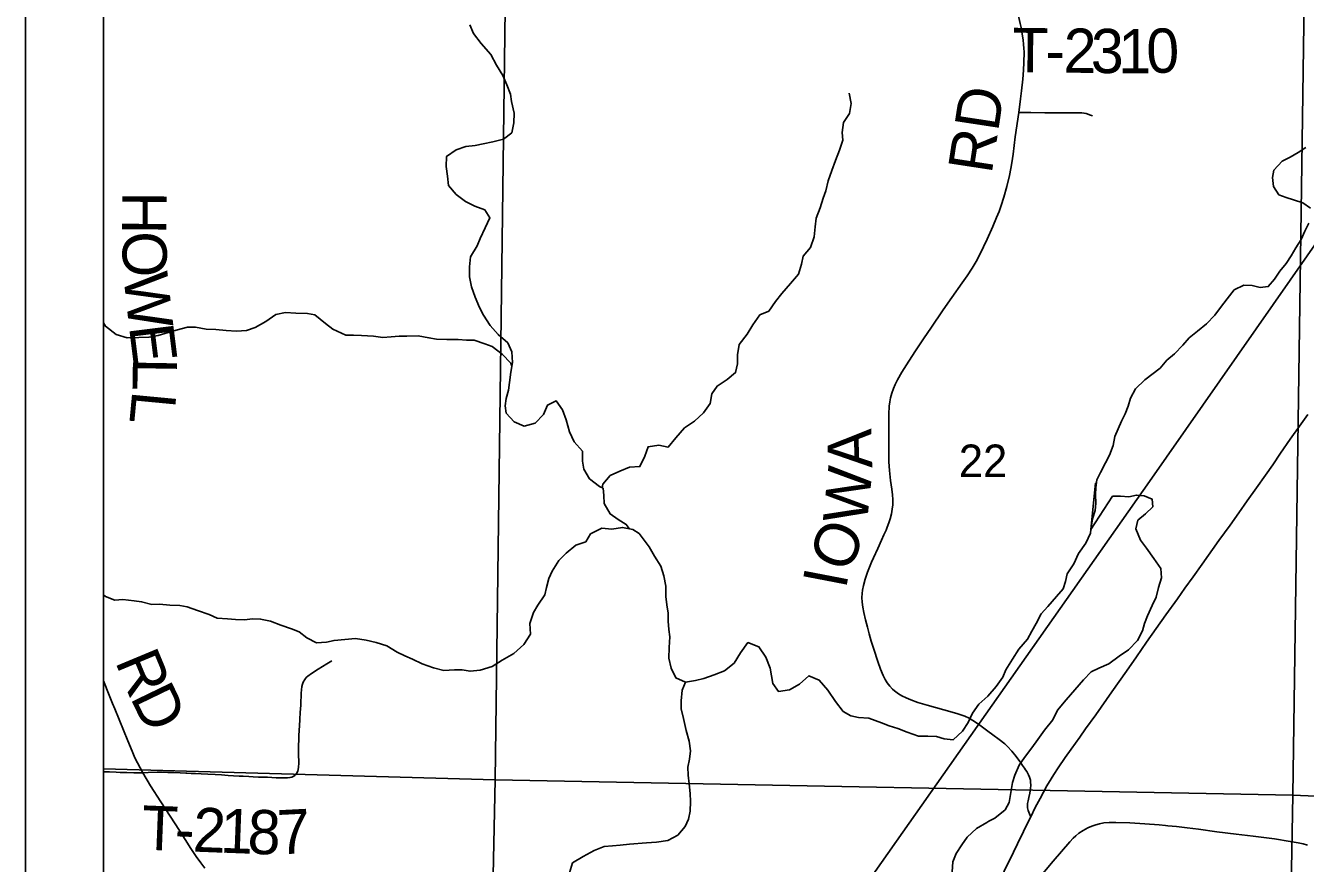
# Model space of a CAD drawing. Extents: x 0 to 34, y 0 to 22.
# Drawn here: x 23.417 to 25.06, y 16.636 to 17.712 of the extents above; entities that cross this region are included whole.
import ezdxf

# ---------------------------------------------------------------- set-up
doc = ezdxf.new("R2010")
doc.units = 0
for name, color, linetype in [('GM_X_Corporation', 7, 'Continuous'), ('GM_X_County_Road', 7, 'Continuous'), ('GM_X_County_Road_Text', 7, 'Continuous'), ('GM_X_Minor_River', 7, 'Continuous'), ('GM_X_Rail_Line', 7, 'Continuous'), ('GM_X_Section_Text', 7, 'Continuous'), ('GM_X_State_Route', 7, 'Continuous'), ('GM_X_Township_Road', 7, 'Continuous'), ('GM_X_Township_Road_Text', 7, 'Continuous'), ('SH_Data', 7, 'Continuous')]:
    doc.layers.add(name, color=color, linetype=linetype)

msp = doc.modelspace()

# ---------------------------------------------------------------- linework, layer by layer
at = {"layer": 'GM_X_Corporation'}
for points in [[(30.3167, 20.9), (23.5167, 20.9), (23.5167, 14.7114), (24.6586, 14.6808), (24.6805, 14.6799), (26.0522, 14.6391), (26.4447, 14.6283), (26.4468, 14.6272), (26.4498, 14.6263), (26.4544, 14.6257), (26.5226, 14.6248), (26.5325, 14.6248), (26.5616, 14.6241), (26.5684, 14.624), (26.5727, 14.624), (26.5813, 14.6239), (26.5991, 14.6234), (26.6128, 14.6229), (26.6208, 14.6225), (26.6337, 14.622), (26.643, 14.6216), (26.6535, 14.621), (27.01, 14.6164)], [(23.5167, 20.7862), (23.5167, 14.7114), (24.6586, 14.6808), (24.6805, 14.6799), (26.0522, 14.6391), (26.4447, 14.6283), (26.4468, 14.6272), (26.4498, 14.6263), (26.4544, 14.6257), (26.5226, 14.6248), (26.5325, 14.6248), (26.5616, 14.6241), (26.5684, 14.624), (26.5727, 14.624), (26.5813, 14.6239), (26.5991, 14.6234), (26.6128, 14.6229), (26.6208, 14.6225), (26.6337, 14.622), (26.643, 14.6216), (26.6535, 14.621), (27.01, 14.6164)]]:
    msp.add_lwpolyline(points, dxfattribs=at)
for points in [[(23.5167, 17.7813), (23.5167, 16.7576), (24.0196, 16.7435), (24.0329, 17.7663)], [(24.0329, 17.7663), (25.0591, 17.7438), (25.0442, 16.7237), (24.0196, 16.7435)], [(26.075, 17.7146), (26.0652, 16.6798), (25.0442, 16.7237), (25.0591, 17.7438)], [(23.5167, 16.7576), (23.5167, 15.7361), (23.9985, 15.7225), (24.0196, 16.7435)], [(24.0196, 16.7435), (25.0442, 16.7237), (25.0261, 15.6992), (23.9985, 15.7225)], [(25.0442, 16.7237), (26.0652, 16.6798), (26.0458, 15.6621), (25.0261, 15.6992)]]:
    msp.add_lwpolyline(points, close=True, dxfattribs=at)
at = {"layer": 'GM_X_County_Road'}
for points in [[(23.5673, 16.7525), (23.5571, 16.772), (23.5534, 16.7805), (23.5479, 16.7937), (23.5312, 16.8346), (23.5284, 16.8415), (23.524, 16.8524), (23.5167, 16.8705)], [(23.6469, 16.6302), (23.6416, 16.637), (23.6358, 16.6451), (23.629, 16.6555), (23.6143, 16.6785), (23.5903, 16.7155), (23.5773, 16.7359), (23.5673, 16.7525)]]:
    msp.add_lwpolyline(points, dxfattribs=at)
at = {"layer": 'GM_X_Minor_River'}
for points in [[(24.1586, 17.1181), (24.1537, 17.1203), (24.1411, 17.1301), (24.1338, 17.1426), (24.1318, 17.1528), (24.1318, 17.1657), (24.1211, 17.1774), (24.1153, 17.1903), (24.111, 17.2058), (24.1064, 17.2187), (24.0983, 17.23), (24.087, 17.2246), (24.0818, 17.2128), (24.0712, 17.2017), (24.0572, 17.1978), (24.0443, 17.2031), (24.034, 17.2144), (24.0328, 17.2239), (24.0339, 17.2334), (24.0368, 17.244), (24.0383, 17.2539), (24.0401, 17.2668), (24.0419, 17.2793), (24.041, 17.293), (24.036, 17.3047), (24.0238, 17.3153), (24.0135, 17.327), (24.0047, 17.3402), (23.9997, 17.35), (23.9939, 17.3633), (23.9893, 17.3765), (23.9869, 17.3894), (23.9868, 17.4023), (23.9883, 17.4152), (23.9965, 17.429), (24.0006, 17.4385), (24.007, 17.4522), (24.013, 17.4651), (24.0064, 17.4753), (23.9935, 17.4802), (23.9817, 17.4862), (23.9695, 17.4952), (23.96, 17.5065), (23.9584, 17.5187), (23.9568, 17.5312), (23.9574, 17.5441), (23.9699, 17.5525), (23.982, 17.5568), (23.9941, 17.558), (24.0043, 17.56), (24.0168, 17.5627), (24.0305, 17.5662), (24.041, 17.5743), (24.0436, 17.5872), (24.0443, 17.5997), (24.0407, 17.6145), (24.0395, 17.624), (24.0349, 17.6361), (24.0295, 17.6478), (24.0215, 17.6611), (24.0142, 17.6747), (24.002, 17.689), (23.992, 17.7018), (23.9874, 17.7128)], [(24.1574, 17.1186), (24.1582, 17.1234), (24.1676, 17.1344), (24.1801, 17.1398), (24.1922, 17.1452), (24.2058, 17.1457), (24.2122, 17.159), (24.2163, 17.1712), (24.2299, 17.1732), (24.242, 17.1706), (24.2518, 17.1828), (24.2631, 17.1954), (24.2759, 17.2042), (24.2876, 17.2146), (24.2959, 17.2268), (24.2981, 17.2393), (24.3048, 17.2492), (24.3177, 17.2577), (24.3286, 17.2665), (24.3312, 17.2775), (24.3311, 17.2893), (24.3333, 17.3026), (24.3434, 17.3159), (24.3509, 17.3277), (24.3599, 17.3407), (24.3713, 17.3453), (24.3799, 17.3579), (24.3882, 17.3678), (24.3991, 17.3808), (24.4092, 17.3927), (24.4133, 17.4056), (24.4152, 17.4159), (24.4249, 17.4269), (24.4294, 17.4406), (24.4308, 17.4535), (24.4323, 17.4646), (24.4371, 17.4779), (24.4412, 17.4904), (24.4445, 17.4999), (24.4475, 17.5125), (24.4523, 17.5258), (24.4568, 17.5387), (24.462, 17.5521), (24.4665, 17.565), (24.4656, 17.5749), (24.4671, 17.5874), (24.4749, 17.5992), (24.4771, 17.6118), (24.4744, 17.6254)], [(25.067, 17.4774), (25.0571, 17.4845), (25.0454, 17.4882), (25.0359, 17.4911), (25.0264, 17.4948), (25.0195, 17.5053), (25.0183, 17.5171), (25.0201, 17.5265), (25.0306, 17.538), (25.0411, 17.5431), (25.0513, 17.5492), (25.0611, 17.5554)], [(24.7849, 17.0652), (24.787, 17.0789), (24.7903, 17.0892), (24.7914, 17.0987), (24.7909, 17.1093), (24.7912, 17.1188), (24.7926, 17.1286), (24.7971, 17.1381), (24.8038, 17.1507), (24.809, 17.1606), (24.8134, 17.1728), (24.8156, 17.1842), (24.82, 17.1941), (24.8241, 17.204), (24.8289, 17.2135), (24.833, 17.2234), (24.8359, 17.2337), (24.8422, 17.2455), (24.8542, 17.257), (24.8738, 17.2723), (24.8827, 17.2823), (24.8925, 17.2907), (24.903, 17.3018), (24.9112, 17.3113), (24.9221, 17.3198), (24.9334, 17.329), (24.9442, 17.3401), (24.9513, 17.35), (24.9599, 17.3611), (24.9689, 17.3726), (24.9813, 17.3788), (24.9919, 17.3781), (25.0025, 17.3756), (25.0127, 17.3768), (25.021, 17.3864), (25.0277, 17.3967), (25.0359, 17.4066), (25.0422, 17.4165), (25.0482, 17.4268), (25.0549, 17.4375), (25.0597, 17.4482), (25.0649, 17.4584)], [(24.0412, 17.2746), (24.04, 17.2786), (24.0289, 17.2903), (24.016, 17.3), (24.0065, 17.3034), (23.9928, 17.3079), (23.9829, 17.3082), (23.9723, 17.3089), (23.9579, 17.3091), (23.9443, 17.3094), (23.9348, 17.3113), (23.9207, 17.3138), (23.9063, 17.3133), (23.8965, 17.3133), (23.8862, 17.3125), (23.8756, 17.3116), (23.8635, 17.3131), (23.8483, 17.3141), (23.8377, 17.3144), (23.8278, 17.3147), (23.8115, 17.3222), (23.8019, 17.3297), (23.7882, 17.3406), (23.7787, 17.3425), (23.7639, 17.3427), (23.7507, 17.3434), (23.7382, 17.3411), (23.7254, 17.3319), (23.7114, 17.3242), (23.7004, 17.3203), (23.6875, 17.3195), (23.6742, 17.3205), (23.661, 17.3219), (23.6488, 17.3222), (23.6348, 17.3248), (23.6246, 17.3247), (23.6102, 17.3208), (23.6, 17.3181), (23.5871, 17.3142), (23.575, 17.3119), (23.5621, 17.3114), (23.5473, 17.3113), (23.5329, 17.3154), (23.5195, 17.3259), (23.5167, 17.3305)], [(24.1918, 17.0661), (24.1881, 17.0716), (24.1778, 17.0779), (24.1676, 17.0851), (24.1599, 17.0983), (24.1594, 17.1086), (24.1586, 17.1181)], [(24.8429, 17.0658), (24.8452, 17.0769), (24.855, 17.085), (24.8647, 17.0942), (24.8635, 17.104), (24.8533, 17.1084), (24.8434, 17.1091), (24.8336, 17.1071), (24.823, 17.1077), (24.8128, 17.1076), (24.7849, 17.0652), (24.7908, 17.1244), (24.7915, 17.1233)], [(24.2048, 17.0599), (24.1965, 17.0652), (24.1832, 17.0677), (24.1696, 17.0654), (24.1567, 17.0668), (24.1424, 17.0593)], [(24.6525, 16.8509), (24.6632, 16.8636), (24.6718, 16.8755), (24.6759, 16.885), (24.6842, 16.8983), (24.6924, 16.9113), (24.7037, 16.9243), (24.7089, 16.9346), (24.7145, 16.9445), (24.7213, 16.9567), (24.7295, 16.9662), (24.7408, 16.9788), (24.7495, 16.9888), (24.7524, 16.9983), (24.7546, 17.0082), (24.7629, 17.0208), (24.7692, 17.0341), (24.7786, 17.0475), (24.7846, 17.0604), (24.7849, 17.0652)], [(24.6537, 16.6906), (24.6617, 16.6944), (24.6749, 16.7051), (24.6802, 16.7146), (24.6827, 16.7298), (24.6842, 16.7401), (24.6871, 16.7496), (24.6927, 16.7622), (24.6998, 16.7721), (24.7092, 16.7847), (24.7167, 16.7954), (24.7254, 16.8072), (24.7359, 16.8206), (24.7419, 16.8331), (24.7531, 16.8465), (24.7644, 16.8591), (24.7753, 16.8721), (24.7855, 16.8821), (24.7953, 16.8871), (24.8078, 16.8925), (24.8214, 16.9025), (24.8331, 16.9105), (24.8447, 16.9224), (24.8511, 16.935), (24.8537, 16.9445), (24.8578, 16.954), (24.8637, 16.9673), (24.869, 16.978), (24.8719, 16.9905), (24.8756, 17.0031), (24.8748, 17.0148), (24.8656, 17.0277), (24.8564, 17.0409), (24.8487, 17.0514), (24.8429, 17.0658)], [(24.1424, 17.0593), (24.1361, 17.049), (24.1232, 17.0447), (24.1112, 17.0348), (24.1015, 17.0252), (24.0929, 17.0114), (24.0889, 17.0019), (24.0856, 16.9905), (24.0838, 16.981), (24.0748, 16.968), (24.0689, 16.9585), (24.0645, 16.9444), (24.065, 16.9308), (24.0568, 16.9174), (24.0437, 16.9056), (24.029, 16.8971), (24.0158, 16.8893), (24.0007, 16.8843), (23.9875, 16.883), (23.9773, 16.8848), (23.9674, 16.8847), (23.9538, 16.8841), (23.9405, 16.8874), (23.9261, 16.8926), (23.9136, 16.8985), (23.9037, 16.9026), (23.8938, 16.9074), (23.8808, 16.9156), (23.8668, 16.92), (23.8539, 16.9229), (23.8406, 16.925), (23.8266, 16.9237), (23.813, 16.9225), (23.8032, 16.9205), (23.7903, 16.9196), (23.7778, 16.9259), (23.7682, 16.9337), (23.7583, 16.9374), (23.7447, 16.9422), (23.7314, 16.9474), (23.7185, 16.9499), (23.7083, 16.9502), (23.6977, 16.9489), (23.6863, 16.9496), (23.6761, 16.9502), (23.6628, 16.9512), (23.6526, 16.956), (23.6374, 16.9612), (23.6241, 16.9656), (23.6146, 16.9674), (23.6021, 16.968), (23.5885, 16.969), (23.5786, 16.9689), (23.5657, 16.9722), (23.5562, 16.9732), (23.5415, 16.975), (23.5313, 16.9741), (23.5191, 16.9789), (23.5167, 16.9811)], [(24.6521, 16.8505), (24.6525, 16.8509), (24.6412, 16.8409), (24.633, 16.8291), (24.6275, 16.8173), (24.62, 16.8062), (24.608, 16.7951), (24.5966, 16.7961), (24.5868, 16.7994), (24.5754, 16.7997), (24.5637, 16.7996), (24.5489, 16.8047), (24.5371, 16.8095), (24.5257, 16.8128), (24.5162, 16.8169), (24.4999, 16.8228), (24.4866, 16.8238), (24.4767, 16.8256), (24.4668, 16.8315), (24.4569, 16.8443), (24.4469, 16.8586), (24.4361, 16.8714), (24.4228, 16.8773), (24.4105, 16.8662), (24.3977, 16.8592), (24.3837, 16.8572), (24.3764, 16.8673), (24.3732, 16.887), (24.3673, 16.901), (24.3585, 16.9145), (24.3444, 16.9197), (24.3347, 16.9067), (24.3269, 16.8934), (24.3145, 16.8837), (24.301, 16.8783), (24.2878, 16.8736), (24.2772, 16.8712), (24.2643, 16.8688), (24.2518, 16.8744), (24.246, 16.8868), (24.2428, 16.8997), (24.2431, 16.9137), (24.2441, 16.927), (24.2428, 16.9368), (24.242, 16.9474), (24.2422, 16.9577), (24.2402, 16.9683), (24.239, 16.9789), (24.2388, 16.9921), (24.2364, 17.0054), (24.2325, 17.0178), (24.2244, 17.0306), (24.2175, 17.0427), (24.2048, 17.0599)], [(24.2643, 16.8688), (24.2599, 16.8589), (24.2589, 16.8449), (24.2586, 16.8346), (24.2618, 16.8222), (24.265, 16.807), (24.2689, 16.7931), (24.2709, 16.7806), (24.2695, 16.7703), (24.2674, 16.7597), (24.2678, 16.7495), (24.2691, 16.7385), (24.2704, 16.726), (24.2708, 16.7157), (24.2702, 16.7032), (24.268, 16.693), (24.264, 16.6835), (24.2546, 16.6727), (24.2414, 16.6658), (24.2271, 16.6637), (24.2142, 16.6628), (24.1923, 16.6611), (24.1802, 16.6595), (24.1704, 16.659), (24.1598, 16.6581), (24.147, 16.653), (24.1327, 16.6453), (24.1191, 16.6368), (24.1151, 16.6243)], [(24.6537, 16.6906), (24.6515, 16.6887), (24.6379, 16.6813), (24.6259, 16.6698), (24.6192, 16.6603), (24.6118, 16.6488), (24.6077, 16.6382), (24.6067, 16.6253)]]:
    msp.add_lwpolyline(points, dxfattribs=at)
at = {"layer": 'GM_X_Rail_Line'}
msp.add_lwpolyline([(27.3181, 19.0787), (26.8719, 18.963), (26.6364, 18.9022), (26.5984, 18.8925), (26.5599, 18.88), (26.5181, 18.863), (26.4939, 18.8489), (26.4659, 18.8316), (26.3299, 18.7221), (25.6255, 18.1395), (25.5717, 18.0909), (25.5316, 18.0529), (25.4885, 18.0044), (25.4477, 17.9591), (25.4146, 17.9181), (25.3806, 17.8712), (24.8603, 17.1266), (24.3577, 16.4125), (24.3204, 16.3658), (24.2794, 16.3248), (24.2417, 16.292), (23.9897, 16.0983), (23.6678, 15.8432), (23.5167, 15.7235)], dxfattribs=at)
at = {"layer": 'GM_X_State_Route'}
for points in [[(24.7077, 16.6961), (24.7136, 16.7079), (24.7196, 16.7195), (24.7285, 16.7358), (24.7338, 16.7449), (24.7375, 16.7506), (24.7429, 16.7589), (24.7521, 16.7721), (24.7595, 16.7828), (24.7706, 16.7984), (24.7781, 16.809), (24.7913, 16.8271), (24.812, 16.8566), (24.8307, 16.883), (24.8436, 16.9013), (24.8566, 16.9202), (24.8812, 16.9553), (24.896, 16.9761), (24.9057, 16.9897), (24.9162, 17.0044), (24.9278, 17.0205), (24.9495, 17.0508), (24.9637, 17.0705), (24.9748, 17.0863), (24.9858, 17.102), (24.9977, 17.1187), (25.0092, 17.1349), (25.0185, 17.1482), (25.0287, 17.163), (25.041, 17.1809), (25.0529, 17.1976), (25.0637, 17.2128)], [(24.6527, 16.5382), (24.6518, 16.5422), (24.6514, 16.5445), (24.651, 16.5479), (24.651, 16.5504), (24.6512, 16.5554), (24.6516, 16.5621), (24.6522, 16.5669), (24.6528, 16.5713), (24.6535, 16.5755), (24.6543, 16.5798), (24.6552, 16.5832), (24.656, 16.5863), (24.6568, 16.5889), (24.6577, 16.5916), (24.6596, 16.5968), (24.6629, 16.6041), (24.6737, 16.6265), (24.6855, 16.6505), (24.6909, 16.6616), (24.7061, 16.6929), (24.7077, 16.6961)], [(24.7211, 16.6207), (24.7366, 16.6392), (24.7581, 16.6641), (24.7623, 16.6687), (24.7655, 16.6717), (24.7693, 16.675), (24.7751, 16.6787), (24.7812, 16.682), (24.7863, 16.6843), (24.7911, 16.6859), (24.7959, 16.6872), (24.8015, 16.6883), (24.8083, 16.6889), (24.8171, 16.6889), (24.835, 16.6882), (24.8542, 16.687), (24.8727, 16.6856), (24.8807, 16.6848), (24.8838, 16.6845), (24.8949, 16.6836), (24.9085, 16.6821), (24.9233, 16.6801), (24.9467, 16.677), (24.9714, 16.6738), (24.9936, 16.6711), (25.0207, 16.6677), (25.041, 16.6645), (25.0514, 16.6625), (25.0575, 16.6612), (25.063, 16.6598)]]:
    msp.add_lwpolyline(points, dxfattribs=at)
at = {"layer": 'GM_X_Township_Road'}
for points in [[(24.6924, 17.6002), (24.6947, 17.6178), (24.6959, 17.6283), (24.6974, 17.643), (24.6982, 17.6548), (24.6989, 17.6647), (24.6991, 17.6777), (24.6988, 17.6829), (24.6985, 17.6877), (24.6979, 17.6938), (24.6964, 17.7036), (24.6953, 17.7097), (24.6943, 17.7146), (24.6917, 17.7262), (24.6897, 17.7352), (24.6882, 17.7406), (24.6865, 17.7459), (24.6847, 17.7511)], [(24.7077, 16.6961), (24.707, 16.6976), (24.706, 16.6999), (24.7045, 16.7042), (24.7037, 16.7075), (24.7034, 16.71), (24.7035, 16.713), (24.7042, 16.7167), (24.7051, 16.7209), (24.7064, 16.7264), (24.7075, 16.7325), (24.7078, 16.7368), (24.7076, 16.7405), (24.7072, 16.743), (24.7061, 16.7472), (24.705, 16.75), (24.7025, 16.7543), (24.7011, 16.7564), (24.6998, 16.7585), (24.6973, 16.7621), (24.6948, 16.7656), (24.6888, 16.7736), (24.6834, 16.7803), (24.6778, 16.7862), (24.6743, 16.7897), (24.667, 16.7955), (24.6591, 16.8014), (24.6525, 16.8061), (24.6405, 16.8149), (24.6334, 16.8199), (24.6286, 16.8228), (24.6229, 16.8252), (24.6141, 16.8282), (24.6069, 16.8303), (24.5747, 16.8395), (24.5627, 16.843), (24.5539, 16.8461), (24.5477, 16.8488), (24.5421, 16.8516), (24.5378, 16.8541), (24.5328, 16.8578), (24.53, 16.8602), (24.5266, 16.8638), (24.5232, 16.8683), (24.5207, 16.8725), (24.5181, 16.8775), (24.5148, 16.8855), (24.5113, 16.8955), (24.506, 16.9114), (24.5029, 16.9215), (24.5002, 16.931), (24.4979, 16.9394), (24.4956, 16.949), (24.4932, 16.9586), (24.4919, 16.9652), (24.491, 16.9719), (24.4908, 16.9775), (24.491, 16.983), (24.4916, 16.9873), (24.4929, 16.9933), (24.495, 17.0011), (24.4982, 17.0104), (24.5006, 17.0168), (24.5033, 17.023), (24.5059, 17.0287), (24.5113, 17.0405), (24.5162, 17.0512), (24.5192, 17.058), (24.5219, 17.0643), (24.5233, 17.0678), (24.5254, 17.0736), (24.5272, 17.0789), (24.5287, 17.0849), (24.5299, 17.091), (24.5305, 17.0965), (24.5306, 17.1033), (24.5303, 17.1095), (24.5293, 17.1169), (24.5277, 17.1278), (24.5261, 17.1408), (24.5256, 17.1517), (24.5253, 17.2131), (24.5258, 17.2232), (24.5266, 17.2287), (24.5276, 17.2342), (24.5293, 17.2402), (24.5314, 17.246), (24.5336, 17.2512), (24.5366, 17.2573), (24.5422, 17.267), (24.548, 17.2765), (24.5587, 17.2932), (24.5709, 17.3113), (24.5792, 17.3236), (24.5954, 17.3471), (24.6064, 17.3629), (24.6196, 17.3817), (24.626, 17.3909), (24.6325, 17.4007), (24.6376, 17.4092), (24.6414, 17.4163), (24.6472, 17.428), (24.6516, 17.4376), (24.659, 17.454), (24.6639, 17.4654), (24.667, 17.4735), (24.6697, 17.4811), (24.6731, 17.4918), (24.677, 17.5055), (24.6804, 17.5194), (24.6823, 17.5285), (24.6836, 17.5358), (24.6851, 17.5469), (24.6879, 17.5691), (24.6924, 17.6002)], [(24.6924, 17.6002), (24.7079, 17.6005), (24.7258, 17.6), (24.7388, 17.6), (24.7506, 17.6001), (24.7642, 17.6001), (24.7735, 17.5999), (24.776, 17.5996), (24.779, 17.599), (24.7843, 17.5971), (24.7872, 17.5961)], [(23.5673, 16.7525), (23.5741, 16.7529), (23.5858, 16.7534), (23.592, 16.7533), (23.5995, 16.7531), (23.6069, 16.7528), (23.615, 16.7525), (23.6224, 16.7522), (23.6236, 16.7522), (23.6292, 16.7519), (23.6348, 16.7517), (23.6422, 16.7513), (23.6509, 16.7508), (23.6602, 16.7503), (23.6682, 16.7498), (23.6769, 16.7493), (23.6837, 16.7489), (23.6911, 16.7484), (23.696, 16.7482), (23.7034, 16.7478), (23.7089, 16.7476), (23.7157, 16.7472), (23.7218, 16.747), (23.7273, 16.7468), (23.7329, 16.7466), (23.7384, 16.7463), (23.7433, 16.7461), (23.7488, 16.746), (23.7532, 16.7461), (23.7562, 16.7464), (23.7586, 16.7471), (23.7603, 16.7478), (23.7623, 16.7491), (23.7632, 16.7499), (23.7648, 16.7518), (23.7662, 16.7545), (23.7668, 16.7569), (23.7673, 16.76), (23.7675, 16.765), (23.7672, 16.7774), (23.7672, 16.7848), (23.7676, 16.7978), (23.7678, 16.8009), (23.768, 16.8065), (23.7689, 16.8207), (23.7695, 16.8307), (23.7696, 16.8338), (23.7701, 16.8405), (23.7708, 16.8548), (23.7711, 16.8591), (23.7715, 16.8635), (23.7722, 16.8665), (23.773, 16.8688), (23.7752, 16.8726), (23.7772, 16.8749), (23.779, 16.8766), (23.784, 16.8802), (23.7924, 16.8856), (23.8034, 16.8926), (23.8098, 16.8963)], [(23.5167, 16.754), (23.5175, 16.7539), (23.5243, 16.7537), (23.533, 16.7533), (23.538, 16.7531), (23.5466, 16.7529), (23.5559, 16.7527), (23.5673, 16.7525)], [(24.6527, 16.5382), (24.6518, 16.5422), (24.6514, 16.5445), (24.651, 16.5479), (24.651, 16.5504), (24.6512, 16.5554), (24.6516, 16.5621), (24.6522, 16.5669), (24.6528, 16.5713), (24.6535, 16.5755), (24.6543, 16.5798), (24.6552, 16.5832), (24.656, 16.5863), (24.6568, 16.5889), (24.6577, 16.5916), (24.6596, 16.5968), (24.6629, 16.6041), (24.6737, 16.6265), (24.6855, 16.6505), (24.6909, 16.6616), (24.7061, 16.6929), (24.7077, 16.6961)]]:
    msp.add_lwpolyline(points, dxfattribs=at)
at = {"layer": 'SH_Data'}
for points in [[(23.4167, 21), (30.4167, 21), (30.4167, 14), (23.4167, 14)], [(23.5167, 20.9), (30.3167, 20.9), (30.3167, 14.1), (23.5167, 14.1)]]:
    msp.add_lwpolyline(points, close=True, dxfattribs=at)

# ---------------------------------------------------------------- texts
at = {"layer": 'GM_X_County_Road_Text'}
for s, rotation, p in [('H', 269.5519, (23.541, 17.4992)), ('O', 271.2638, (23.5406, 17.4473)), ('W', 276.3355, (23.5421, 17.3918)), ('E', 277.1066, (23.5494, 17.3256)), ('L', 269.0657, (23.5546, 17.2855)), ('L', 264.6137, (23.5539, 17.2442)), ('R', 292.619, (23.5311, 16.8958)), ('D', 295.8185, (23.5505, 16.8496))]:
    msp.add_text(s, height=0.0568, rotation=rotation, dxfattribs=at).set_placement(p)
at = {"layer": 'GM_X_Section_Text'}
msp.add_text('22', height=0.04186, rotation=0, dxfattribs=at).set_placement((24.6153, 17.1322))
at = {"layer": 'GM_X_Township_Road_Text'}
for s, height, rotation, p in [('T', 0.0568, 359.2993, (24.6837, 17.6524)), ('2', 0.0568, 359.3203, (24.7495, 17.6516)), ('3', 0.0568, 359.474, (24.7847, 17.6512)), ('1', 0.0568, 359.9802, (24.8202, 17.6509)), ('0', 0.0568, 1.5368, (24.8569, 17.6509)), ('-', 0.0568, 359.2974, (24.7262, 17.6519)), ('RD', 0.05682, 81.3193, (24.6574, 17.5204)), ('A', 0.0568, 91.4742, (24.5042, 17.1443)), ('W', 0.0568, 84.1385, (24.4972, 17.0709)), ('O', 0.0568, 67.5438, (24.4737, 17.0073)), ('I', 0.0568, 79.0996, (24.4702, 16.9873)), ('T', 0.0568, 357.7473, (23.565, 16.6541)), ('2', 0.0568, 357.769, (23.6308, 16.6515)), ('1', 0.0568, 357.8406, (23.6659, 16.6502)), ('8', 0.0568, 358.0262, (23.7011, 16.6488)), ('7', 0.0568, 2.9406, (23.7414, 16.6477)), ('-', 0.0568, 357.7512, (23.6075, 16.6524))]:
    msp.add_text(s, height=height, rotation=rotation, dxfattribs=at).set_placement(p)

doc.saveas('drawing.dxf')
